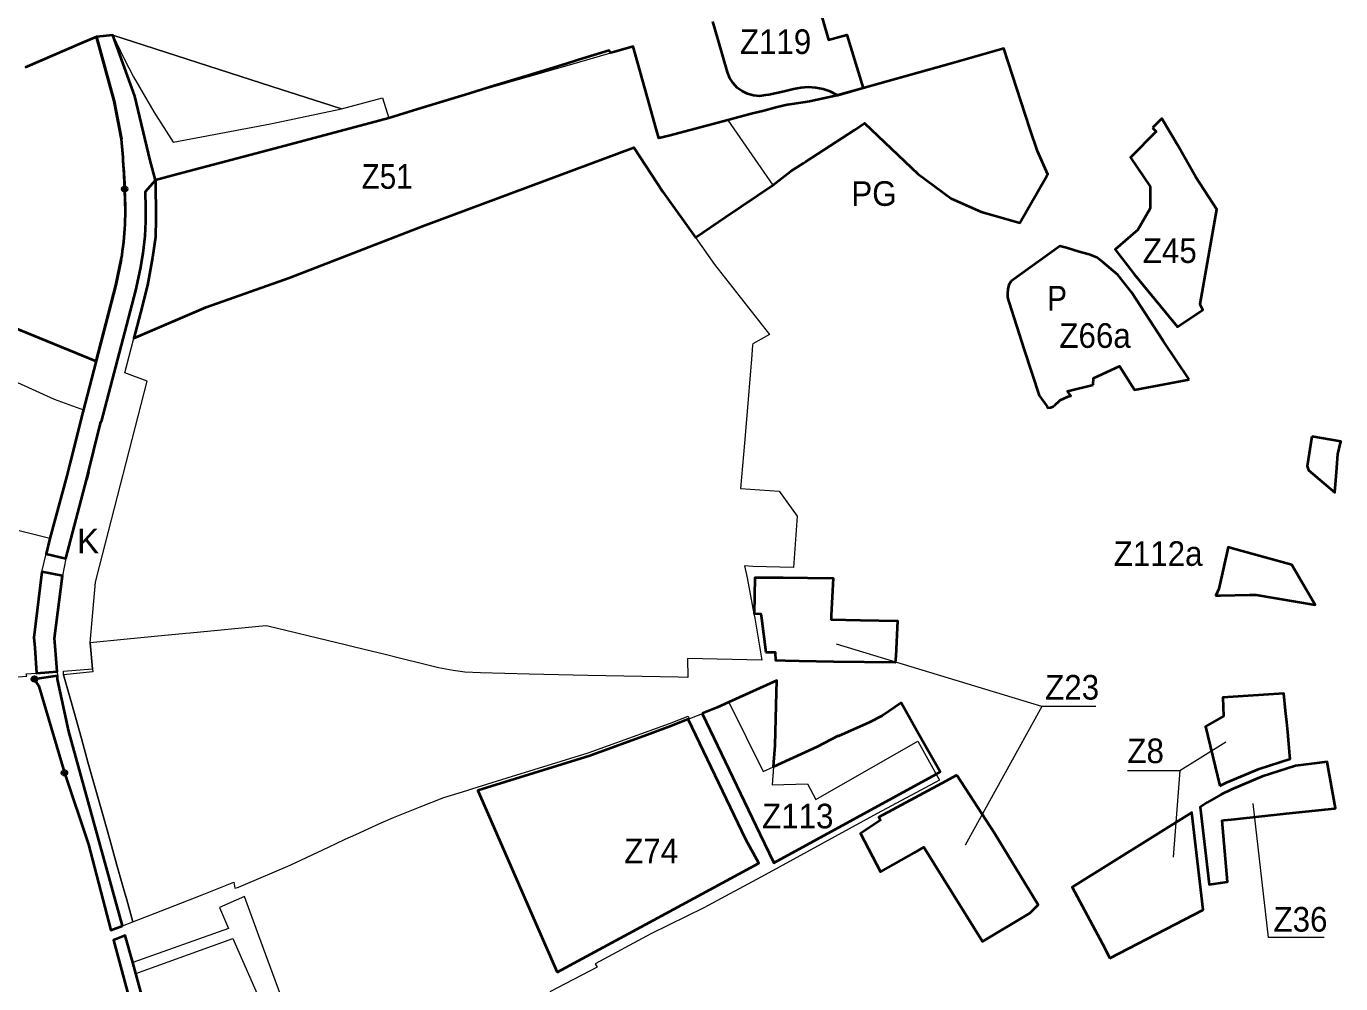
# Model space of a CAD drawing. Extents: x -650276 to -642489, y -1074425 to -1066658.
# Drawn here: x -649154 to -647874, y -1070685 to -1069752 of the extents above; entities that cross this region are included whole.
import ezdxf

# ---------------------------------------------------------------- set-up
doc = ezdxf.new("R2010")
doc.units = 0
doc.header["$LTSCALE"] = 9.6
doc.header["$PDMODE"] = 32
doc.header["$PDSIZE"] = 4.8
for name, color, linetype, lineweight in [('1', 7, 'Continuous', 13), ('43', 7, 'Continuous', 13), ('44', 7, 'Continuous', 40), ('45', 7, 'Continuous', 40), ('46', 7, 'Continuous', 13), ('47', 7, 'Continuous', 13), ('60', 7, 'Continuous', 35)]:
    doc.layers.add(name, color=color, linetype=linetype, lineweight=lineweight)

msp = doc.modelspace()

# ---------------------------------------------------------------- linework, layer by layer
at = {"layer": '1'}
msp.add_line((-648916.03, -1069847.12), (-648846.924, -1069832.58), dxfattribs=at)
for points in [[(-649154.76, -1069792.11), (-649085.41, -1069762.44), (-649069.4, -1069760.67), (-648914.48, -1069810.75), (-648856.932, -1069829.35), (-648846.924, -1069832.58), (-648806.946, -1069821.79), (-648800.85, -1069841.52), (-648772.48, -1069832.83), (-648722.24, -1069817.54), (-648614.79, -1069786.74), (-648584.65, -1069778.1), (-648562.87, -1069771.85), (-648546.97, -1069828.68), (-648541.06, -1069849.78), (-648537.86, -1069861.22), (-648470.79, -1069843.51), (-648426.82, -1069906.88), (-648438.08, -1069914.49), (-648472.6, -1069937.81), (-648502.048, -1069957.969), (-648483.5, -1069983.99), (-648429.961, -1070052.299)], [(-648846.924, -1069832.58), (-648856.932, -1069829.35), (-648914.48, -1069810.75), (-649069.4, -1069760.67)], [(-649069.4, -1069760.67), (-649058.34, -1069783.72), (-649049.22, -1069801.23), (-649029.61, -1069835.47), (-649010.55, -1069865.09), (-648916.03, -1069847.12)], [(-648429.96, -1070052.3), (-648446.46, -1070061.45), (-648446.57, -1070062.84), (-648447.65, -1070076.76), (-648448.57, -1070087.65)], [(-648448.57, -1070087.65), (-648451.61, -1070123.56), (-648454.55, -1070158.24), (-648458.28, -1070202.26), (-648420.7, -1070204.96), (-648403.04, -1070229.15), (-648406.8, -1070279.32), (-648446.18, -1070278.15), (-648454.458, -1070277.747), (-648451.89, -1070289.22), (-648445.28, -1070324.46), (-648444.49, -1070328.69), (-648437.54, -1070369.65), (-648509.96, -1070367.805), (-648509.678, -1070386.34), (-648518.98, -1070386.16), (-648606.95, -1070384.45), (-648664.06, -1070383.09), (-648711.58, -1070381.95), (-648726.83, -1070381.36), (-648738.09, -1070379.56), (-648752.45, -1070376.96), (-648762.64, -1070374.39), (-648792.76, -1070366.81), (-648803.08, -1070364.33), (-648834.08, -1070356.86), (-648844.53, -1070354.34), (-648851.29, -1070352.71), (-648918.59, -1070336.5), (-648920.42, -1070336.06), (-648994.11, -1070343.24), (-648998.39, -1070343.66), (-649028.75, -1070346.62), (-649058.61, -1070349.53), (-649091.46, -1070352.73), (-649089.07, -1070377.88), (-649088.792, -1070380.804), (-649117.36, -1070383.93), (-649109.76, -1070411.05), (-649102.31, -1070437.61), (-649100.01, -1070445.82), (-649093.59, -1070468.73), (-649086.55, -1070493.85), (-649079.51, -1070518.97), (-649072.47, -1070544.09), (-649065.42, -1070569.21), (-649058.38, -1070594.33), (-649055.93, -1070603.08), (-649049.96, -1070624.38), (-649016.38, -1070611.46), (-648982.48, -1070598.08), (-648951.64, -1070585.69), (-648950.49, -1070591.66), (-648947.93, -1070590.8), (-648945.37, -1070589.94), (-648944.71, -1070589.72), (-648940.08, -1070587.75), (-648898.99, -1070570.25), (-648896.08, -1070569.01), (-648859.5, -1070551.65), (-648843.2, -1070543.91), (-648832.96, -1070539.25), (-648808.11, -1070528.06), (-648796.05, -1070522.63), (-648770.34, -1070512.39), (-648747.22, -1070503.19), (-648724.84, -1070496.31), (-648719.84, -1070494.77), (-648685.48, -1070484.2), (-648606.55, -1070459.91), (-648527.6, -1070431.05), (-648509.26, -1070424.06), (-648508.278, -1070426.53), (-648481.18, -1070415.62), (-648469.77, -1070410.47), (-648436.22, -1070478.01), (-648426.05, -1070473.34), (-648427.41, -1070491.08), (-648393.14, -1070490.07), (-648385.085, -1070505.351), (-648285.75, -1070448.49), (-648264.56, -1070486.34), (-648325.21, -1070518.84), (-648434.43, -1070578.53), (-648494.04, -1070610.73), (-648545.76, -1070636.22), (-648599.66, -1070665.32), (-648597.74, -1070668.62), (-648643.953, -1070692.685)]]:
    msp.add_lwpolyline(points, dxfattribs=at)
at = {"layer": '44'}
for p, q in [((-649058.858, -1069889.759), (-649057.868, -1069910.51)), ((-649057.134, -1069932.873), (-649057.868, -1069910.51)), ((-649146.163, -1070347.543), (-649145.424, -1070357.637))]:
    msp.add_line(p, q, dxfattribs=at)
for points in [[(-649061.138, -1069979.243), (-649061.138, -1069979.243), (-649061.139, -1069979.254), (-649066.487, -1070004.267), (-649098.65, -1070127.795), (-649110.925, -1070177.113), (-649114.174, -1070189.816), (-649130.712, -1070250.935), (-649134.294, -1070266.095), (-649115.159, -1070270.568), (-649095.152, -1070193.731), (-649093.095, -1070186.132), (-649095.152, -1070193.731), (-649080.924, -1070137.409), (-649080.38, -1070136.996), (-649047.131, -1070009.304), (-649042.468, -1069988.477), (-649042.468, -1069988.477), (-649039.966, -1069973.035), (-649037.98, -1069956.626), (-649037.322, -1069942.129), (-649037.137, -1069928.996), (-649037.665, -1069912.977), (-649028.017, -1069902.109), (-649032.928, -1069882.782), (-649048, -1069820), (-649069.4, -1069760.67), (-649085.41, -1069762.44), (-649068, -1069825.147), (-649060.897, -1069861.994)], [(-649138.43, -1070283.6), (-649146.163, -1070347.543), (-649146.163, -1070347.543)], [(-649125.503, -1070355.837), (-649126.069, -1070348.097), (-649118.257, -1070287.455), (-649138.43, -1070283.6)], [(-649145.424, -1070357.637), (-649143.633, -1070382.123), (-649123.693, -1070380.572), (-649125.503, -1070355.837)], [(-649059.951, -1070628.223), (-649112.14, -1070439.152), (-649123.138, -1070388.16), (-649123.385, -1070384.775), (-649145.73, -1070387.91)], [(-649145.73, -1070387.91), (-649141.48, -1070394.84), (-649132.07, -1070426.81), (-649116.56, -1070479.19)], [(-649116.56, -1070479.19), (-649093.2, -1070549.1), (-649071.33, -1070632.6), (-649059.951, -1070628.223)], [(-649025.129, -1070754.377), (-649047.11, -1070674.743), (-649050.081, -1070663.981), (-649057.338, -1070637.689), (-649068.65, -1070642.23), (-649068.65, -1070642.23), (-649054.31, -1070696.44)]]:
    msp.add_lwpolyline(points, dxfattribs=at)
for centre, radius, start, end in [((-649633.43, -1069918.001), 575.266, 2.81398, 5.58706), ((-649347.129, -1069931.193), 290, 350.46253, 4.08974), ((-649347.129, -1069931.193), 290, 359.66809, 4.08974)]:
    msp.add_arc(centre, radius, start, end, dxfattribs=at)
for p in [(-649145.73, -1070387.91), (-649116.56, -1070479.19)]:
    msp.add_point(p, dxfattribs=at)
at = {"layer": '45'}
msp.add_line((-649057.868, -1069910.51), (-649058.82, -1069890.548), dxfattribs=at)
for points in [[(-648388.514, -1069709.779), (-648372.522, -1069765.283), (-648354.898, -1069760.328), (-648338.933, -1069812.492), (-648363.563, -1069819.352), (-648371.093, -1069815.602), (-648377.983, -1069813.332), (-648385.093, -1069811.952), (-648392.333, -1069811.482), (-648399.563, -1069811.922), (-648406.723, -1069813.272), (-648414.54, -1069815.288), (-648415.873, -1069815.632), (-648430.764, -1069818.704), (-648433.853, -1069819.342), (-648439.773, -1069820.012), (-648445.683, -1069819.552), (-648451.413, -1069818.022), (-648456.763, -1069815.432), (-648461.523, -1069811.902), (-648465.553, -1069807.532), (-648468.703, -1069802.482), (-648470.853, -1069796.942), (-648480.15, -1069765.358), (-648485.323, -1069747.432)], [(-649060.897, -1069861.994), (-649068, -1069825.147), (-649085.41, -1069762.44), (-649085.41, -1069762.44), (-649099.75, -1069768.575), (-649154.76, -1069792.11)], [(-648128.48, -1069971.7), (-648140.96, -1069968.01), (-648147.46, -1069966.19), (-648194.84, -1070000.49)], [(-648111.44, -1069977.32), (-648118.75, -1069974.53), (-648128.48, -1069971.7)], [(-649202.375, -1070030.469), (-649085.737, -1070078.201), (-649066.487, -1070004.267), (-649061.139, -1069979.254), (-649061.138, -1069979.243), (-649061.138, -1069979.243)], [(-648021.35, -1070096.14), (-648046.83, -1070058.62), (-648077.68, -1070011.06), (-648091.06, -1069994.07), (-648105.79, -1069981.56), (-648111.44, -1069977.32)], [(-648194.84, -1070000.49), (-648197.19, -1070003.94), (-648198.17, -1070008.05), (-648198.48, -1070012.3), (-648198.22, -1070016.4), (-648197.23, -1070020.37), (-648182.01, -1070067.11)], [(-648182.01, -1070067.11), (-648167.48, -1070111.75), (-648159.89, -1070122.49), (-648159.02, -1070123.71), (-648156.07, -1070123.54)], [(-648115.11, -1070101.26), (-648114.7, -1070094.68), (-648089.22, -1070083.27), (-648074.76, -1070106.17), (-648021.35, -1070096.14)], [(-648152.35, -1070121.05), (-648147.02, -1070116.35), (-648139.45, -1070112.79), (-648136.61, -1070111.97), (-648139.91, -1070107.48), (-648115.11, -1070101.26)], [(-648156.07, -1070123.54), (-648153.85, -1070122.38), (-648152.35, -1070121.05)]]:
    msp.add_lwpolyline(points, dxfattribs=at)
for points in [[(-648906.547, -1069869.711), (-649007.37, -1069896.602), (-649028.017, -1069902.109), (-649027.457, -1069939.468), (-649028.007, -1069957.455), (-649030.869, -1069977.253), (-649035.775, -1070004.354), (-649042.536, -1070031.342), (-649048.918, -1070055.852), (-648978.654, -1070025.669), (-648897.735, -1069997.25), (-648767.83, -1069946.87), (-648562.242, -1069870.301), (-648533.79, -1069913.49), (-648502.048, -1069957.969), (-648472.6, -1069937.81), (-648426.82, -1069906.88), (-648409.44, -1069893.25), (-648396.87, -1069885.43), (-648395.03, -1069884.22), (-648347.06, -1069853), (-648337.48, -1069846.531), (-648285.62, -1069895.71), (-648253.13, -1069919.7), (-648223.99, -1069932.96), (-648218.245, -1069934.595), (-648186.268, -1069943.697), (-648160.04, -1069897.73), (-648159.1, -1069896.39), (-648169.15, -1069873.81), (-648176.78, -1069851.74), (-648201.83, -1069773.86), (-648247.27, -1069786.64), (-648251.94, -1069787.95), (-648339.05, -1069812.45), (-648363.68, -1069819.31), (-648365.81, -1069819.9), (-648391.08, -1069825.45), (-648408.45, -1069827.83), (-648412.74, -1069828.72), (-648422.75, -1069830.78), (-648435.53, -1069834.44), (-648447.98, -1069837.44), (-648470.79, -1069843.51), (-648528.11, -1069858.73), (-648537.86, -1069861.22), (-648541.06, -1069849.78), (-648546.97, -1069828.68), (-648562.87, -1069771.85), (-648579.63, -1069776.66), (-648584.65, -1069778.1), (-648586.09, -1069775.75), (-648593.59, -1069778.06), (-648615.88, -1069784.93), (-648627.99, -1069788.67), (-648665.05, -1069799.99), (-648698.31, -1069810.16), (-648722.24, -1069817.54), (-648772.48, -1069832.83), (-648800.85, -1069841.52)], [(-648057.11, -1069851.12), (-648053.61, -1069854.64), (-648078.54, -1069880.01), (-648059.32, -1069908.27), (-648059.5, -1069929.52), (-648071.58, -1069950.39), (-648093.67, -1069969.42), (-648074.96, -1069993.46), (-648032.85, -1070044.73), (-648008.18, -1070028.25), (-648010.44, -1070023.66), (-648010.94, -1070022.65), (-647994.71, -1069930.53), (-648015.11, -1069898.98), (-648032.94, -1069867.46), (-648048.08, -1069841.95)], [(-648057.11, -1069851.12), (-648053.61, -1069854.64), (-648078.54, -1069880.01), (-648059.32, -1069908.27), (-648059.5, -1069929.52), (-648071.58, -1069950.39), (-648093.67, -1069969.42), (-648074.96, -1069993.46), (-648032.85, -1070044.73), (-648008.18, -1070028.25), (-648010.44, -1070023.66), (-648010.94, -1070022.65), (-647994.71, -1069930.53), (-648015.11, -1069898.98), (-648032.94, -1069867.46), (-648048.08, -1069841.95)], [(-647902.17, -1070151.64), (-647906.6, -1070180.65), (-647905.17, -1070184.5), (-647879.81, -1070206.08), (-647878.18, -1070186.33), (-647876.74, -1070168.88), (-647873.97, -1070156.58)], [(-647902.17, -1070151.64), (-647906.6, -1070180.65), (-647905.17, -1070184.5), (-647879.81, -1070206.08), (-647878.18, -1070186.33), (-647876.74, -1070168.88), (-647873.97, -1070156.58)], [(-647962.82, -1070305.9), (-647956.36, -1070305.77), (-647898.82, -1070315.51), (-647921.51, -1070276.76), (-647979.24, -1070260.71), (-647983.6, -1070259.5), (-647992.71, -1070300.01), (-647995.46, -1070306.55), (-647991.12, -1070306.46)], [(-648444.85, -1070324.47), (-648444.15, -1070289.16), (-648428.98, -1070288.92), (-648416.93, -1070288.85), (-648392.94, -1070289.25), (-648368.25, -1070289.71), (-648370.07, -1070325.94), (-648370.07, -1070329.902), (-648341.46, -1070330.48), (-648305.47, -1070331.23), (-648307.13, -1070365.57), (-648307.67, -1070371.78), (-648367.67, -1070371.16), (-648401.35, -1070370.5), (-648414.75, -1070370.24), (-648424.05, -1070370), (-648424.31, -1070362.21), (-648433.46, -1070361.94), (-648437.65, -1070328.8), (-648438.296, -1070324.598)], [(-648444.85, -1070324.47), (-648444.15, -1070289.16), (-648428.98, -1070288.92), (-648416.93, -1070288.85), (-648392.94, -1070289.25), (-648368.25, -1070289.71), (-648370.07, -1070325.94), (-648370.07, -1070329.902), (-648341.46, -1070330.48), (-648305.47, -1070331.23), (-648307.13, -1070365.57), (-648307.67, -1070371.78), (-648367.67, -1070371.16), (-648401.35, -1070370.5), (-648414.75, -1070370.24), (-648424.05, -1070370), (-648424.31, -1070362.21), (-648433.46, -1070361.94), (-648437.65, -1070328.8), (-648438.296, -1070324.598)], [(-648495.666, -1070421.476), (-648439.409, -1070538.729), (-648425.835, -1070567.021), (-648267.801, -1070480.55), (-648263.859, -1070478.393), (-648282.01, -1070446.35), (-648302.01, -1070411.05), (-648320.24, -1070423.64), (-648332.97, -1070430.18), (-648362.79, -1070443.63), (-648363.1, -1070443.1), (-648383.61, -1070453.86), (-648426.05, -1070473.34), (-648425.71, -1070468.87), (-648424.47, -1070452.7), (-648423.56, -1070413.35), (-648423.005, -1070389.357), (-648469.77, -1070410.47), (-648481.18, -1070415.62)], [(-647991.539, -1070492.016), (-647985.19, -1070488.804), (-647953.251, -1070475.276), (-647923.247, -1070465.749), (-647923.53, -1070462.75), (-647924.63, -1070451.09), (-647925.5, -1070439.63), (-647926.53, -1070429.76), (-647927.67, -1070418.74), (-647929.24, -1070401.97), (-647988.86, -1070405.95), (-647988.11, -1070423.93), (-648005.668, -1070434.145)], [(-648636.757, -1070673.431), (-648550.72, -1070626.869), (-648440.531, -1070567.236), (-648452.97, -1070544.21), (-648509.227, -1070426.957), (-648526.28, -1070433.85), (-648538.611, -1070438.388), (-648546.377, -1070441.246), (-648604.92, -1070462.79), (-648714.161, -1070496.376), (-648655.178, -1070631.294)], [(-647950.48, -1070482.79), (-647980.4, -1070495.463), (-647990.295, -1070500.352), (-648003.85, -1070508.218), (-648010.831, -1070512.588), (-648002, -1070588), (-647984.03, -1070585.46), (-647989.5, -1070525.73), (-647987.436, -1070525.508), (-647977.41, -1070524.43), (-647927.14, -1070519), (-647889.27, -1070514.92), (-647879.89, -1070513.91), (-647879.16, -1070513.83), (-647887.08, -1070468.54), (-647899.87, -1070470.04), (-647917.98, -1070472.47)], [(-648247.67, -1070481.57), (-648262.69, -1070489.67), (-648323.59, -1070522.48), (-648322.18, -1070525.44), (-648341.41, -1070538.42), (-648322.16, -1070575.76), (-648289.22, -1070557.15), (-648279.736, -1070551.783), (-648278.89, -1070553.14), (-648222.58, -1070643.48), (-648176.54, -1070616.09), (-648168.575, -1070607.847), (-648211, -1070538)], [(-648247.67, -1070481.57), (-648262.69, -1070489.67), (-648323.59, -1070522.48), (-648322.18, -1070525.44), (-648341.41, -1070538.42), (-648322.16, -1070575.76), (-648289.22, -1070557.15), (-648279.736, -1070551.783), (-648278.89, -1070553.14), (-648222.58, -1070643.48), (-648176.54, -1070616.09), (-648168.575, -1070607.847), (-648211, -1070538)], [(-648098.637, -1070659.682), (-648007.838, -1070612.851), (-648019, -1070518), (-648135.47, -1070590.61), (-648105.98, -1070645.91)]]:
    msp.add_lwpolyline(points, close=True, dxfattribs=at)
for centre, radius, start, end in [((-649649.71, -1069919.176), 591.583, 2.77379, 5.54687), ((-649347.129, -1069931.193), 290, 350.46253, 4.08974)]:
    msp.add_arc(centre, radius, start, end, dxfattribs=at)
msp.add_point((-649057.868, -1069910.51), dxfattribs=at)
at = {"layer": '46'}
for p, q in [((-648165.109, -1070414.543), (-648239.52, -1070549.62)), ((-648165.109, -1070414.543), (-648239.52, -1070549.62)), ((-648030.462, -1070477.049), (-648036.992, -1070561.483)), ((-647944.293, -1070639.492), (-647959.279, -1070509.201)), ((-647890.215, -1070639.492), (-647944.293, -1070639.492)), ((-647890.215, -1070639.492), (-647904.43, -1070639.492))]:
    msp.add_line(p, q, dxfattribs=at)
for points in [[(-648112.329, -1070414.543), (-648165.109, -1070414.543), (-648364.98, -1070353.932)], [(-648112.329, -1070414.543), (-648165.109, -1070414.543), (-648364.98, -1070353.932)], [(-648081.63, -1070477.049), (-648030.462, -1070477.049), (-647985.902, -1070448.995)]]:
    msp.add_lwpolyline(points, dxfattribs=at)
at = {"layer": '47'}
msp.add_line((-649115.159, -1070270.568), (-649118.257, -1070287.455), dxfattribs=at)
for points in [[(-649057.722, -1070089.665), (-649048.918, -1070055.852), (-649037.411, -1070011.659), (-649032.972, -1069991.835), (-649028.007, -1069957.455), (-649027.566, -1069943.013), (-649027.135, -1069928.902), (-649027.569, -1069915.721), (-649028.017, -1069902.109), (-649037.665, -1069912.977), (-649037.137, -1069928.996), (-649037.199, -1069933.38), (-649037.322, -1069942.129), (-649037.98, -1069956.626), (-649039.623, -1069970.202), (-649042.468, -1069988.477), (-649047.131, -1070009.304), (-649055.689, -1070042.169), (-649061.354, -1070063.169), (-649067.061, -1070085.844), (-649079.268, -1070132.727), (-649080.38, -1070136.996), (-649080.872, -1070137.37), (-649083.089, -1070145.979)], [(-649296.851, -1069931.092), (-649289.95, -1069948.146), (-649243.846, -1070062.071), (-649126.437, -1070115.217), (-649126.437, -1070115.217), (-649098.101, -1070125.688), (-649085.737, -1070078.201), (-649202.375, -1070030.469)], [(-649089.07, -1070377.88), (-649091.46, -1070352.73), (-649086.157, -1070293.589), (-649082.233, -1070278.265), (-649036.031, -1070097.854), (-649057.722, -1070089.665)], [(-649083.089, -1070145.979), (-649095.152, -1070193.731), (-649093.095, -1070186.132), (-649095.152, -1070193.731), (-649111.303, -1070255.758), (-649095.152, -1070193.731), (-649115.159, -1070270.568)], [(-649202.969, -1070388.965), (-649153.11, -1070385.21), (-649153.64, -1070382.9), (-649143.633, -1070382.123), (-649146.163, -1070347.543), (-649138.43, -1070283.6), (-649134.294, -1070266.095), (-649130.712, -1070250.935), (-649160.748, -1070243.413)], [(-649118.257, -1070287.455), (-649126.069, -1070348.097), (-649125.503, -1070355.837), (-649123.693, -1070380.572)], [(-649123.693, -1070380.572), (-649123.385, -1070384.775), (-649123.138, -1070388.16), (-649112.14, -1070439.152), (-649059.951, -1070628.223), (-649049.96, -1070624.38), (-649055.93, -1070603.08), (-649058.38, -1070594.33), (-649065.42, -1070569.21), (-649072.47, -1070544.09), (-649079.51, -1070518.97), (-649086.55, -1070493.85), (-649093.59, -1070468.73), (-649100.01, -1070445.82), (-649102.31, -1070437.61), (-649109.76, -1070411.05), (-649117.36, -1070383.93), (-649117.374, -1070380.081), (-649089.07, -1070377.88)]]:
    msp.add_lwpolyline(points, dxfattribs=at)
msp.add_lwpolyline([(-649014.888, -1070782.994), (-648966.35, -1070764.7), (-648908.94, -1070740.19), (-648892.215, -1070733.293), (-648927.2, -1070637.98), (-648941.064, -1070599.735), (-648965.569, -1070610.382), (-648956.687, -1070630.825), (-649050.081, -1070663.981), (-649047.11, -1070674.743), (-648952.455, -1070640.564), (-648922.196, -1070710.207), (-648924.668, -1070712.022), (-648943.837, -1070720.104), (-649025.129, -1070754.377)], close=True, dxfattribs=at)

# ---------------------------------------------------------------- texts
at = {"layer": '43'}
msp.add_text('K', height=24, dxfattribs=at).set_placement((-649104.211, -1070265.34))
at = {"layer": '46'}
for s, width, p in [('Z119', 0.95, (-648458.914, -1069779.092)), ('Z51', 0.9, (-648827.214, -1069910.388)), ('Z45', 0.95, (-648066.663, -1069982.614)), ('Z45', 0.95, (-648066.663, -1069982.614)), ('Z66a', 0.95, (-648147.889, -1070065.308)), ('Z112a', 0.95, (-648094.972, -1070277.658)), ('Z23', 0.95, (-648161.708, -1070407.912)), ('Z23', 0.95, (-648161.708, -1070407.912)), ('Z8', 0.95, (-648081.661, -1070469.822)), ('Z113', 0.95, (-648437.324, -1070533.384)), ('Z113', 0.95, (-648437.324, -1070533.384)), ('Z74', 0.95, (-648571.565, -1070567.472)), ('Z36', 0.95, (-647939.415, -1070633.92)), ('Z36', 0.95, (-647939.415, -1070633.92))]:
    msp.add_text(s, height=24, dxfattribs=dict(at, width=width)).set_placement(p)
at = {"layer": '60'}
for s, width, p in [('PG', 0.95, (-648350.408, -1069926.995)), ('P', 0.9, (-648159.699, -1070028.97))]:
    msp.add_text(s, height=24, dxfattribs=dict(at, width=width)).set_placement(p)

doc.saveas('drawing.dxf')
